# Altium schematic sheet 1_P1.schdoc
size 309 x 223 mm; Symbol: Sheet-Symbol_A4; Device: Sheet-Symbol_A4; Company: EasyEDA.com; Drawed: EasyEDA Pro; Reviewed: EasyEDA Pro; Version: V0.1; Page Size: A4; @Project Name: esp32-hub75-driver-schem_2022-11-10_17-33-28; @Page Count: 1; @Update Date: 2022-12-31; @Create Date: 2022-12-31; @Schematic Name: Schematic1; Part Number: JLCPCB-002; @Page No: 1; @Page Name: P1
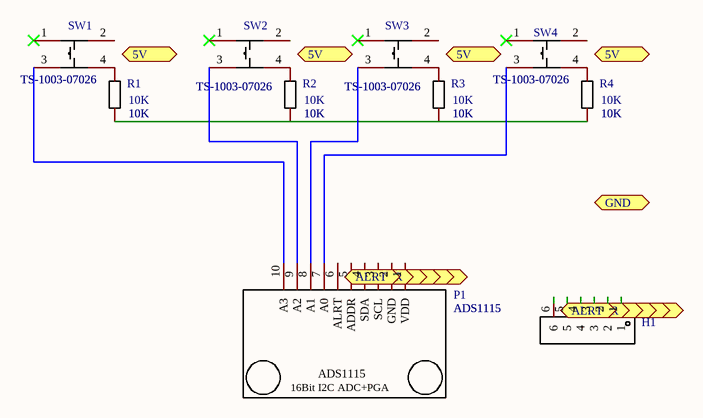
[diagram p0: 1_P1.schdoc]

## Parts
H1  HDR-F_2.54_1x6P  [HDR-TH_6P-P2.54-V-F]  (value not drawn)
P1  ADS1115  [ADS1115 BREAKOUT BOARD]
R1  10K  [R0603]
R2  10K  [R0603]
R3  10K  [R0603]
R4  10K  [R0603]
SW1  TS-1003-07026  [KEY-TH_4P-L12.0-W12.0-P5.00-LS12.5]
SW2  TS-1003-07026  [KEY-TH_4P-L12.0-W12.0-P5.00-LS12.5]
SW3  TS-1003-07026  [KEY-TH_4P-L12.0-W12.0-P5.00-LS12.5]
SW4  TS-1003-07026  [KEY-TH_4P-L12.0-W12.0-P5.00-LS12.5]

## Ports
5V (bidir), ADDR (bidir), ALRT (bidir), GND (bidir), SCL (bidir), SDA (bidir)

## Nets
NetP1_7: P1.7(A0) SW4.3
NetP1_8: P1.8(A1) SW3.3
NetP1_9: P1.9(A2) SW2.3
NetP1_10: P1.10(A3) SW1.3
NetR1_1: R1.1 R2.1 R3.1 R4.1
NetR1_2: R1.2 SW1.4
NetR2_2: R2.2 SW2.4
NetR3_2: R3.2 SW3.4
NetR4_2: R4.2 SW4.4

Not connected (* = marked no-connect by the designer): H1 1 2 3 4 5 6; P1 1(VDD) 2(GND) 3(SCL) 4(SDA) 5(ADDR) 6(ALRT); SW1 1* 2; SW2 1* 2; SW3 1* 2; SW4 1* 2

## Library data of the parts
H1 = HDR-F_2.54_1x6P: Symbol: Header-Female-2.54_1x6; Convert to PCB: yes
P1 = ADS1115: Add into BOM: yes
R1-R4 = Res_0603: Symbol: Res; Convert to PCB: yes
SW1-SW4 = TS-1003-07026: Contact Current:50mA Voltage Rating (DC):12V Circuit:SPST Mounting Style:Straight Actuator Style:Round Button With Lamp:- Switch Length:12mm Switch Width:12mm Switch Height:7mm; Manufacturer: XUNPU(讯普); Add into BOM: yes; Contact Current: 50mA; Voltage Rating (DC): 12V; Circuit: SPST; Switch Length: 12mm; Switch Height: 7mm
